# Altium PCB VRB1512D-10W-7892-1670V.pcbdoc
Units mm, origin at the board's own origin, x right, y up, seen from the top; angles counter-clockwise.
Board outline 80 x 45 mm, 2 copper layers (Top Layer, Bottom Layer), stack 0.78 mm thick; 36 components, 14 nets, 88 pads, 145 vias.
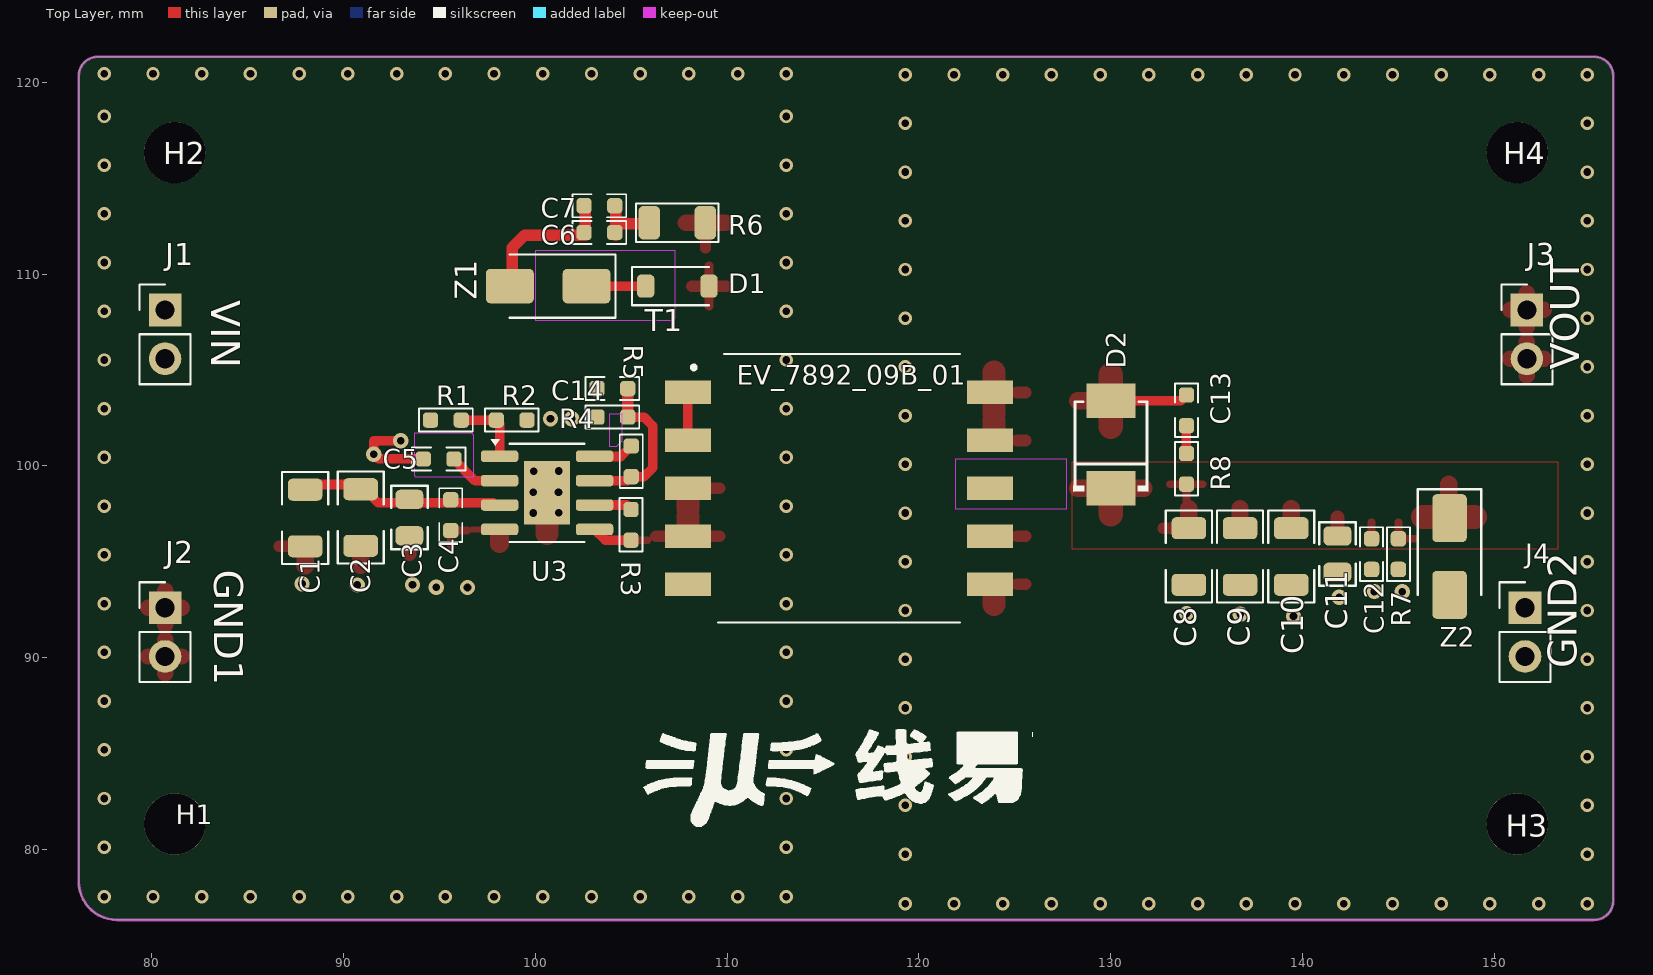
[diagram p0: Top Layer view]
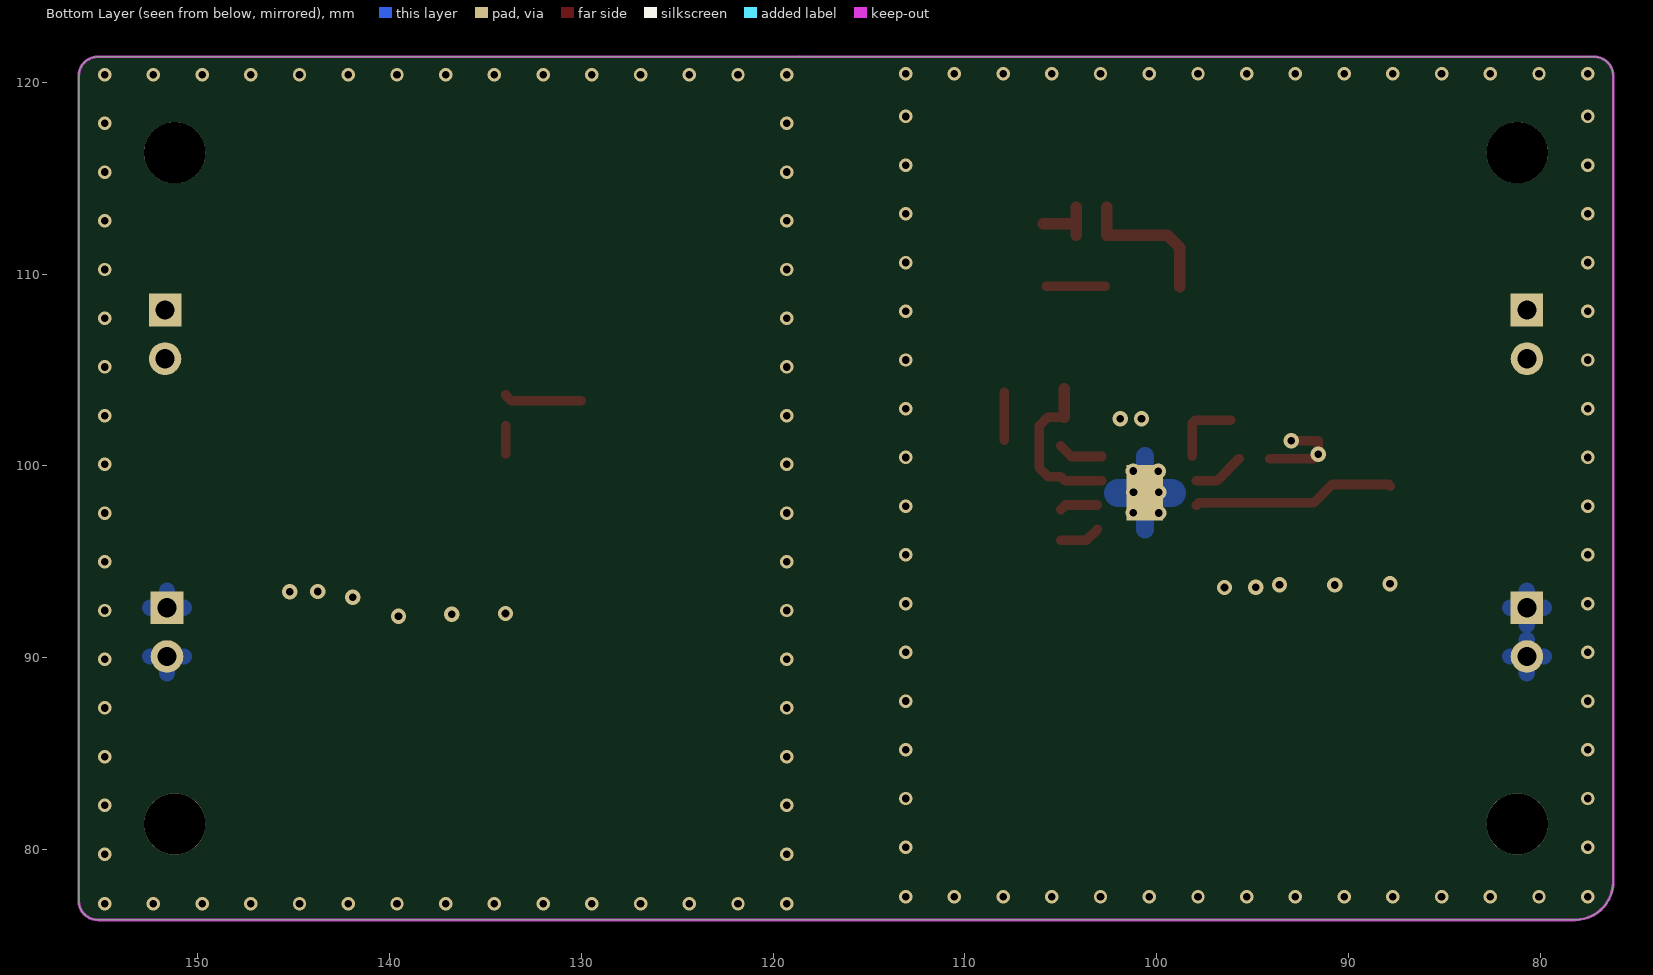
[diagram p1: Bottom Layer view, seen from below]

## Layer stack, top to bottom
Top Solder Mask Layer: solder mask 0.01, Dk 3.3
Top Layer: signal copper 0.035
Dielectric1: surface 0.71, FR4, Dk 4.5
Bottom Layer: signal copper 0.035
Bottom Solder Mask Layer: solder mask 0.01, Dk 3.3

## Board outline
76.2,120.327 cw(c77.2,120.327) 77.2,121.327 155.2,121.327 cw(c155.2,120.327) 156.2,120.327 156.2,77.327 cw(c155.2,77.327) 155.2,76.327 78.2,76.327 cw(c78.2,78.327) 76.2,78.327

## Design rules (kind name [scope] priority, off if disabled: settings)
BoardOutlineClearance safeClearance [All] p0: genericclearance=0.254 ignorepadtopadclearanceinfootprint=FALSE except(0: Arc-SplitContinuation Track-SplitContinuation SMDPad-SplitContinuation THPad-SplitContinuation Via-SplitContinuation Fill-SplitContinuation Poly-SplitContinuation Region-SplitContinuation Text-SplitContinuation)
BoardOutlineClearance Plane_innerPlane [All] p0: genericclearance=0.254 ignorepadtopadclearanceinfootprint=FALSE except(0: Arc-SplitContinuation Track-SplitContinuation SMDPad-SplitContinuation THPad-SplitContinuation Via-SplitContinuation Fill-SplitContinuation Poly-SplitContinuation Region-SplitContinuation Text-SplitContinuation)
BoardOutlineClearance Copper_CopperRegion [All] p0: genericclearance=0.254 ignorepadtopadclearanceinfootprint=FALSE except(0: Arc-SplitContinuation Track-SplitContinuation SMDPad-SplitContinuation THPad-SplitContinuation Via-SplitContinuation Fill-SplitContinuation Poly-SplitContinuation Region-SplitContinuation Text-SplitContinuation)
BoardOutlineClearance Copper_CopperRegion1 [All] p0: genericclearance=0.254 ignorepadtopadclearanceinfootprint=FALSE except(0: Arc-SplitContinuation Track-SplitContinuation SMDPad-SplitContinuation THPad-SplitContinuation Via-SplitContinuation Fill-SplitContinuation Poly-SplitContinuation Region-SplitContinuation Text-SplitContinuation)
BoardOutlineClearance Copper_CopperRegion2 [All] p0: genericclearance=0.254 ignorepadtopadclearanceinfootprint=FALSE except(0: Arc-SplitContinuation Track-SplitContinuation SMDPad-SplitContinuation THPad-SplitContinuation Via-SplitContinuation Fill-SplitContinuation Poly-SplitContinuation Region-SplitContinuation Text-SplitContinuation)
BoardOutlineClearance Copper_CopperRegion3 [All] p0: genericclearance=0.254 ignorepadtopadclearanceinfootprint=FALSE except(0: Arc-SplitContinuation Track-SplitContinuation SMDPad-SplitContinuation THPad-SplitContinuation Via-SplitContinuation Fill-SplitContinuation Poly-SplitContinuation Region-SplitContinuation Text-SplitContinuation)
BoardOutlineClearance Copper_CopperRegion4 [All] p0: genericclearance=0.254 ignorepadtopadclearanceinfootprint=FALSE except(0: Arc-SplitContinuation Track-SplitContinuation SMDPad-SplitContinuation THPad-SplitContinuation Via-SplitContinuation Fill-SplitContinuation Poly-SplitContinuation Region-SplitContinuation Text-SplitContinuation)
BoardOutlineClearance Copper_CopperRegion5 [All] p0: genericclearance=0.254 ignorepadtopadclearanceinfootprint=FALSE except(0: Arc-SplitContinuation Track-SplitContinuation SMDPad-SplitContinuation THPad-SplitContinuation Via-SplitContinuation Fill-SplitContinuation Poly-SplitContinuation Region-SplitContinuation Text-SplitContinuation)
BoardOutlineClearance Copper_CopperRegion6 [All] p0: genericclearance=0.254 ignorepadtopadclearanceinfootprint=FALSE except(0: Arc-SplitContinuation Track-SplitContinuation SMDPad-SplitContinuation THPad-SplitContinuation Via-SplitContinuation Fill-SplitContinuation Poly-SplitContinuation Region-SplitContinuation Text-SplitContinuation)
BoardOutlineClearance Copper_CopperRegion7 [All] p0: genericclearance=0.254 ignorepadtopadclearanceinfootprint=FALSE except(0: Arc-SplitContinuation Track-SplitContinuation SMDPad-SplitContinuation THPad-SplitContinuation Via-SplitContinuation Fill-SplitContinuation Poly-SplitContinuation Region-SplitContinuation Text-SplitContinuation)
BoardOutlineClearance Copper_CopperRegion8 [All] p0: genericclearance=0.254 ignorepadtopadclearanceinfootprint=FALSE except(0: Arc-SplitContinuation Track-SplitContinuation SMDPad-SplitContinuation THPad-SplitContinuation Via-SplitContinuation Fill-SplitContinuation Poly-SplitContinuation Region-SplitContinuation Text-SplitContinuation)
BoardOutlineClearance Copper_CopperRegion9 [All] p0: genericclearance=0.254 ignorepadtopadclearanceinfootprint=FALSE except(0: Arc-SplitContinuation Track-SplitContinuation SMDPad-SplitContinuation THPad-SplitContinuation Via-SplitContinuation Fill-SplitContinuation Poly-SplitContinuation Region-SplitContinuation Text-SplitContinuation)
BoardOutlineClearance Copper_CopperRegion10 [All] p0: genericclearance=0.254 ignorepadtopadclearanceinfootprint=FALSE except(0: Arc-SplitContinuation Track-SplitContinuation SMDPad-SplitContinuation THPad-SplitContinuation Via-SplitContinuation Fill-SplitContinuation Poly-SplitContinuation Region-SplitContinuation Text-SplitContinuation)
BoardOutlineClearance Copper_CopperRegion11 [All] p0: genericclearance=0.254 ignorepadtopadclearanceinfootprint=FALSE except(0: Arc-SplitContinuation Track-SplitContinuation SMDPad-SplitContinuation THPad-SplitContinuation Via-SplitContinuation Fill-SplitContinuation Poly-SplitContinuation Region-SplitContinuation Text-SplitContinuation)
BoardOutlineClearance otherClearance [All] p0: genericclearance=0.254 ignorepadtopadclearanceinfootprint=FALSE except(0: Arc-SplitContinuation Track-SplitContinuation SMDPad-SplitContinuation THPad-SplitContinuation Via-SplitContinuation Fill-SplitContinuation Poly-SplitContinuation Region-SplitContinuation Text-SplitContinuation)
Clearance safeClearance [All] p1: gap=0.178 ignorepadtopadclearanceinfootprint=FALSE
Clearance Plane_innerPlane [All] p1: gap=0.178 ignorepadtopadclearanceinfootprint=FALSE
Clearance Copper_CopperRegion [All] p1: gap=0.178 ignorepadtopadclearanceinfootprint=FALSE
Clearance Copper_CopperRegion1 [All] p1: gap=0.178 ignorepadtopadclearanceinfootprint=FALSE
Clearance Copper_CopperRegion2 [All] p1: gap=0.178 ignorepadtopadclearanceinfootprint=FALSE
Clearance Copper_CopperRegion3 [All] p1: gap=0.178 ignorepadtopadclearanceinfootprint=FALSE
Clearance Copper_CopperRegion4 [All] p1: gap=0.178 ignorepadtopadclearanceinfootprint=FALSE
Clearance Copper_CopperRegion5 [All] p1: gap=0.178 ignorepadtopadclearanceinfootprint=FALSE
Clearance Copper_CopperRegion6 [All] p1: gap=0.178 ignorepadtopadclearanceinfootprint=FALSE
Clearance Copper_CopperRegion7 [All] p1: gap=0.178 ignorepadtopadclearanceinfootprint=FALSE
Clearance Copper_CopperRegion8 [All] p1: gap=0.178 ignorepadtopadclearanceinfootprint=FALSE
Clearance Copper_CopperRegion9 [All] p1: gap=0.178 ignorepadtopadclearanceinfootprint=FALSE
Clearance Copper_CopperRegion10 [All] p1: gap=0.178 ignorepadtopadclearanceinfootprint=FALSE
Clearance Copper_CopperRegion11 [All] p1: gap=0.178 ignorepadtopadclearanceinfootprint=FALSE
Clearance otherClearance [All] p1: gap=0.178 ignorepadtopadclearanceinfootprint=FALSE
DiffPairsRouting differentialPair [All] p1: maxuncoupledlength=10 minlimit=6 maxlimit=Infinity mostfreqgap=6 toplayer_minwidth=5 toplayer_prefwidth=10 toplayer_maxwidth=100 bottomlayer_minwidth=5 bottomlayer_prefwidth=10 bottomlayer_maxwidth=100
PasteMaskExpansion Common [All] p1: expansion=0
PlaneConnect innerPlane [All] p1: planeconnectstyle=Relief reliefexpansion=0.508 reliefentries=4 reliefconductorwidth=0.254 reliefairgap=0.254
PolygonConnect CopperRegion [All] p1: connectstyle=Direct reliefentries=4 reliefconductorwidth=10 polygonreliefangle="90 Angle" airgapwidth=10
PolygonConnect CopperRegion1 [All] p1: connectstyle=Relief reliefentries=4 reliefconductorwidth=0 polygonreliefangle="90 Angle" airgapwidth=1
PolygonConnect CopperRegion2 [All] p1: connectstyle=Relief reliefentries=4 reliefconductorwidth=0 polygonreliefangle="90 Angle" airgapwidth=1
PolygonConnect CopperRegion3 [All] p1: connectstyle=Direct reliefentries=4 reliefconductorwidth=10 polygonreliefangle="90 Angle" airgapwidth=10
PolygonConnect CopperRegion4 [All] p1: connectstyle=Relief reliefentries=4 reliefconductorwidth=0 polygonreliefangle="90 Angle" airgapwidth=1
PolygonConnect CopperRegion5 [All] p1: connectstyle=Relief reliefentries=4 reliefconductorwidth=0 polygonreliefangle="90 Angle" airgapwidth=1
PolygonConnect CopperRegion6 [All] p1: connectstyle=Relief reliefentries=4 reliefconductorwidth=0 polygonreliefangle="90 Angle" airgapwidth=1
PolygonConnect CopperRegion7 [All] p1: connectstyle=Relief reliefentries=4 reliefconductorwidth=0 polygonreliefangle="90 Angle" airgapwidth=1
PolygonConnect CopperRegion8 [All] p1: connectstyle=Relief reliefentries=4 reliefconductorwidth=0 polygonreliefangle="90 Angle" airgapwidth=1
PolygonConnect CopperRegion9 [All] p1: connectstyle=Relief reliefentries=4 reliefconductorwidth=0 polygonreliefangle="90 Angle" airgapwidth=1
PolygonConnect CopperRegion10 [All] p1: connectstyle=Relief reliefentries=4 reliefconductorwidth=0 polygonreliefangle="90 Angle" airgapwidth=1
PolygonConnect CopperRegion11 [All] p1: connectstyle=Relief reliefentries=4 reliefconductorwidth=0 polygonreliefangle="90 Angle" airgapwidth=1
RoutingVias viaSize [All] p1: viastyle="Through Hole" holewidth=12 minholewidth=11.8 maxholewidth=236.2 width=12 minwidth=11.8 maxwidth=236.2
SolderMaskExpansion Common [All] p1: useseparateexpansions=TRUE expansion=0 expansionbottom=0
Width trackWidth [All] p1: maxlimit=100 minlimit=5 preferedwidth=10

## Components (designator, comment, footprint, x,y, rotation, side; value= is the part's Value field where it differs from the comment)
C1 "" MYLibrary:C1206 88.001,97.28 r270 top
C2 "" C1206 90.896,97.305 r270 top
C3 "" MYLibrary:C0805 93.436,97.305 r270 top
C4 "" C0603 95.595,97.432 r90 top
C5 "" C0603 94.96,100.353 r0 top
C6 "" C0603 103.342,112.164 r180 top
C7 "" MYLibrary:C0603 103.342,113.561 r180 top
C8 "" C1206 134.076,95.273 r270 top
C9 "" C1206 136.743,95.273 r270 top
C10 "" C1206 139.41,95.273 r270 top
C11 "" C0805 141.823,95.4 r270 top
C12 "" C0603 143.601,95.4 r90 top
C13 "" MYLibrary:C0603 133.949,102.893 r90 top
C14 "" C0603 104.02,104.027 r0 top
D1 "" SOD-123_L2.8-W1.8-LS3.7-FD 107.406,109.37 r0 top
D2 "" SMBF_L4.3-W3.6-LS5.3-RD 130.012,101.115 r90 top
H1 "Mechanical_MountingHole" MountingHole:MountingHole_3.2mm_M3_DIN965 81.2,81.327 r0 top
H2 "" MountingHole:MountingHole_3.2mm_M3_DIN965 81.2,116.327 r0 top
H3 "" MountingHole:MountingHole_3.2mm_M3_DIN965 151.2,81.327 r0 top
H4 "" MountingHole:MountingHole_3.2mm_M3_DIN965 151.2,116.327 r0 top
J1 "" ?#1 80.7,108.127 r0 top
J2 "" ?#1 80.7,92.602 r0 top
J3 "" ?#1 151.7,108.127 r0 top
J4 "Connector_Generic_Conn_01x02" Connector_PinHeader_2.54mm:PinHeader_1x02_P2.54mm_Vertical 151.6,92.602 r0 top
R1 "" R0603 95.341,102.385 r0 top
R2 "" MYLibrary:R0603 98.77,102.385 r0 top
R3 "" R0603 104.993,96.924 r270 top
R4 "" R0603 104.02,102.542 r180 top
R5 "" MYLibrary:R0603 105.005,100.237 r270 top
R6 "" R1206 107.406,112.672 r180 top
R7 "" R0603 144.998,95.4 r90 top
R8 "" MYLibrary:R0603 133.949,99.845 r90 top
T1 "" XFMR-SMD_CMB1670V 105.755,106.83 r0 top
U3 "" ?#2 96.916,101.293 r0 top
Z1 "" SMA_L4.4-W2.6-LS5.1-RD 100.675,109.37 r180 top
Z2 "" Diode_SMD:D_SMA 147.665,95.273 r270 top

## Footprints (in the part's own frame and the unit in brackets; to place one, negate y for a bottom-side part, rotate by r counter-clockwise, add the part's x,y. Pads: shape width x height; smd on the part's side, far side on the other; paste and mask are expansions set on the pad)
C0603 [mm]
  rrect50% 0.8x0.8 smd: 1(-0.8,0) 2(0.8,0)
  silkscreen extent -1.4,-0.6 1.4,0.6
C0805 [mm]
  rrect50% 1x1.45 smd: 1(-0.95,0) 2(0.95,0)
  silkscreen extent -1.65,-0.95 1.65,0.96
C1206 [mm]
  rrect43% 1.15x1.8 smd: 1(-1.475,0) 2(1.475,0)
  silkscreen extent -2.4,-1.2 2.4,1.2
Connector_PinHeader_2.54mm:PinHeader_1x02_P2.54mm_Vertical [mm]
  rect 1.7x1.7 hole 1: 1(0,0)
  round 1.7 hole 1: 2(0,-2.54)
  silkscreen extent -1.33,-3.87 1.33,1.33
Diode_SMD:D_SMA [mm]
  rrect27% 2.5x1.8 smd: 1(-2,0) 2(2,0)
  silkscreen extent -3.51,-1.65 2,1.65
MountingHole:MountingHole_3.2mm_M3_DIN965 [mm]
  round 3.2 hole 3.2 unplated: ""(0,0)
MYLibrary:C0603 [mm]
  rrect50% 0.8x0.8 smd: 1(-0.8,0) 2(0.8,0)
  silkscreen extent -1.4,-0.6 1.4,0.6
MYLibrary:C0805 [mm]
  rrect50% 1x1.45 smd: 1(-0.95,0) 2(0.95,0)
  silkscreen extent -1.65,-0.95 1.65,0.96
MYLibrary:C1206 [mm]
  rrect43% 1.15x1.8 smd: 1(-1.475,0) 2(1.475,0)
  silkscreen extent -2.4,-1.2 2.4,1.2
MYLibrary:R0603 [mm]
  rrect50% 0.8x0.8 smd: 1(-0.8,0) 2(0.8,0)
  silkscreen extent -1.4,-0.6 1.4,0.6
R0603 [mm]
  rrect50% 0.8x0.8 smd: 1(-0.8,0) 2(0.8,0)
  silkscreen extent -1.4,-0.6 1.4,0.6
R1206 [mm]
  rrect44% 1.125x1.75 smd: 1(-1.462,0) 2(1.462,0)
  silkscreen extent -2.15,-1 2.15,1
SMA_L4.4-W2.6-LS5.1-RD [mm]
  rrect27% 2.5x1.8 smd: 1(-2,0) 2(2,0)
  silkscreen extent -3.51,-1.65 2,1.65
SMBF_L4.3-W3.6-LS5.3-RD [mm]
  rect 1.8x2.54 smd: 1(-2.285,0) 2(2.285,0)
  silkscreen extent -2.45,-1.95 2.23,1.95
SOD-123_L2.8-W1.8-LS3.7-FD [mm]
  rrect50% 0.9x1.2 smd: 1(-1.65,0) 2(1.65,0)
  silkscreen extent -2.36,-1 1.65,1
XFMR-SMD_CMB1670V [mm]
  rect 2.4x1.22 smd: 1(2.2,-3) 2(2.2,-5.5) 3(2.2,-8) 4(2.2,-10.5) 5(2.2,-13) 6(17.96,-13) 7(17.96,-10.5) 8(17.96,-8) 9(17.96,-5.5) 10(17.96,-3)
  silkscreen extent 2.46,-15 16.38,-1
?#1 [mm]
  rect 1.7x1.7 hole 1: 1(0,0)
  round 1.7 hole 1: 2(0,-2.54)
  silkscreen extent -1.33,-3.87 1.33,1.33
?#2 [mm]
  rrect50% 1.95x0.6 smd: 1(1.225,-0.795) 2(1.225,-2.065) 3(1.225,-3.335) 4(1.225,-4.605) 5(6.175,-4.605) 6(6.175,-3.335) 7(6.175,-2.065) 8(6.175,-0.795)
  rect 2.41x3.3 smd: 9(3.7,-2.7)
  rect 1.9x2.9 smd far side: 9(3.7,-2.7)
  rrect49% 1.01x1.38 smd: ""(3.1,-3.525) ""(3.1,-1.875) ""(4.3,-3.525) ""(4.3,-1.875)
  silkscreen extent 0.76,-5.26 5.65,0.1

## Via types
v1: diameter 0.7, hole 0.4, Top Layer to Bottom Layer, 124 vias
v2: diameter 0.8, hole 0.4, Top Layer to Bottom Layer, 21 vias

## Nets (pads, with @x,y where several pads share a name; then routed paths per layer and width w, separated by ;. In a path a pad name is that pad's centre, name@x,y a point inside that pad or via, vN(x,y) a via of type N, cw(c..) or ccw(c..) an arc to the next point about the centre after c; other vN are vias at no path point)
$1N3972: C6.1 C7.1 R6.2 | length 3.2
  Top Layer w0.25: C6.1@104.192,112.017 C6.1@104.2,112.024
  Top Layer w0.6: C6.1@104.2,112.024 104.2,112.617 ; C7.1@104.2,113.477 104.2,112.617 ; R6.2@105.907,112.617 104.2,112.617
$1N3986: D1.1 Z1.1 | length 3.1
  Top Layer w0.5: Z1.1 D1.1
$1N4011: R1.2 R2.1 U3.1 | length 3.8
  Top Layer w0.5: R1.2 R2.1 98.141,102.214 U3.1
$1N4023: R3.1 U3.6 | length 2
  Top Layer w0.5: U3.6 104.76,97.958 R3.1
$1N4278: C5.2 U3.2 | length 2.7
  Top Layer w0.5: C5.2@95.705,100.377 96.865,99.217 U3.2@97.925,99.217
$1N4425: C13.1 R8.2 | length 1.4
  Top Layer w0.5: R8.2 C13.1
/SEC: C13.2 D2.2 T1.9 T1.10 | length 4.1
  Top Layer w0.5: D2.2 133.656,103.4 C13.2
GND1: C1.2 C2.2 C3.2 C4.1 C5.1 C14.1 J2.1 J2.2 R2.2 R4.2 U3. U3.4 U3.9 | length 4.7
  Top Layer w0.5: v2(92.985,101.307) 91.585,101.307 v2(91.585,100.607) 91.815,100.377 C5.1@94.105,100.377
  other v1: 77.53,77.527 80.07,77.527 82.61,77.527 85.15,77.527 87.69,77.527 90.23,77.527 92.77,77.527 95.31,77.527 97.85,77.527 100.39,77.527 102.93,77.527 105.47,77.527 108.01,77.527 110.55,77.527 113.09,77.527 77.53,80.117 113.09,80.117 77.53,82.657 113.09,82.657 77.53,85.197 113.09,85.197 77.53,87.737 113.09,87.737 77.53,90.277 113.09,90.277 77.53,92.817 113.09,92.817 77.53,95.357 113.09,95.357 77.53,97.897 113.09,97.897 77.53,100.437 113.09,100.437 77.53,102.977 113.09,102.977 77.53,105.517 113.09,105.517 77.53,108.057 113.09,108.057 77.53,110.597 113.09,110.597 77.53,113.137 113.09,113.137 77.53,115.677 113.09,115.677 77.53,118.217 113.09,118.217 77.53,120.44 80.07,120.44 82.61,120.44 85.15,120.44 87.69,120.44 90.23,120.44 92.77,120.44 95.31,120.44 97.85,120.44 100.39,120.44 102.93,120.44 105.47,120.44 108.01,120.44 110.55,120.44 113.09,120.44
  other v2: 96.465,93.657 94.835,93.677 90.715,93.787 93.6,93.797 87.835,93.857 99.894,97.54 101.216,97.55 99.894,98.629 101.213,98.629 99.913,99.718 101.216,99.728 100.795,102.447 101.895,102.447
GND2: C8.2 C9.2 C10.2 C11.2 C12.1 J4.1 J4.2 R7.1 T1.6 T1.7 Z2.2
  other v1: 119.29,77.167 121.83,77.167 124.37,77.167 126.91,77.167 129.45,77.167 131.99,77.167 134.53,77.167 137.07,77.167 139.61,77.167 142.15,77.167 144.69,77.167 147.23,77.167 149.77,77.167 152.31,77.167 154.85,77.167 119.29,79.757 154.85,79.757 119.29,82.297 154.85,82.297 119.29,84.837 154.85,84.837 119.29,87.377 154.85,87.377 119.29,89.917 154.85,89.917 119.29,92.457 154.85,92.457 119.29,94.997 154.85,94.997 119.29,97.537 154.85,97.537 119.29,100.077 154.85,100.077 119.29,102.617 154.85,102.617 119.29,105.157 154.85,105.157 119.29,107.697 154.85,107.697 119.29,110.237 154.85,110.237 119.29,112.777 154.85,112.777 119.29,115.317 154.85,115.317 119.29,117.857 154.85,117.857 119.29,120.397 121.83,120.397 124.37,120.397 126.91,120.397 129.45,120.397 131.99,120.397 134.53,120.397 137.07,120.397 139.61,120.397 142.15,120.397 144.69,120.397 147.23,120.397 149.77,120.397 152.31,120.397 154.85,120.397
  other v2: 139.53,92.164 136.75,92.254 133.95,92.304 141.92,93.154 143.74,93.448 145.2,93.438
RREF: C14.2 R4.1 R5.2 U3.7 | length 8.7
  Top Layer w0.5: U3.7@102.875,99.217 104.785,99.217 R5.2 105.665,99.437 106.125,99.897 106.125,102.087 105.67,102.542 R4.1
  Top Layer w0.6: R4.1 C14.2
SW: D1.2 R3.2 R6.1 T1.3 T1.4 U3.5 | length 2.1
  Top Layer w0.5: U3.5 103.655,96.124 R3.2
TC: R5.1 U3.8 | length 2.4
  Top Layer w0.5: U3.8@102.875,100.487 104.455,100.487 R5.1
VIN: C1.1 C2.1 C3.1 C4.2 C6.2 C7.2 J1.1 J1.2 R1.1 T1.1 T1.2 U3.3 Z1.2 | length 20.6
  Top Layer w0.5: C1.1@87.825,98.942 87.912,99.029 90.855,99.029 91.81,98.074 97.798,98.074 U3.3@97.925,97.947 ; T1.2 T1.1
  Top Layer w0.6: Z1.2@98.787,109.347 98.787,111.364 99.44,112.017 102.592,112.017 102.6,112.024 C7.2@102.6,113.477
VOUT: C8.1 C9.1 C10.1 C11.1 C12.2 D2.1 J3.1 J3.2 R7.2 R8.1 Z2.1
pads on no net: H1. H2. H3. H4. T1.5 T1.8

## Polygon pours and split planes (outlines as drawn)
VOUT on Top Layer (solid, remove dead copper, pour order 0): 153.5,109.927 153.5,95.657 127.799,95.657 127.799,99.6 148.19,99.6 148.19,109.367 148.75,109.927
GND2 on Bottom Layer (solid, remove dead copper, pour order 20): 118.219,121.2 155.819,121.2 155.819,76.2 118.219,76.2
GND2 on Bottom Layer (solid, remove dead copper, pour order 22): 118.542,121.327 118.6,121.327 118.6,121.385
SW on Top Layer (solid, remove dead copper, pour order 2): 106.87,99.437 109.64,99.437 109.895,99.697 109.895,105.587 107.395,108.087 107.395,112.937 107.955,113.497 110.368,113.497 111.505,112.36 111.505,96.357 110.595,95.447 102.14,95.447 101.9,95.687 101.9,96.887 101.96,96.947 106.165,96.947 106.87,97.917
/SEC on Top Layer (solid, remove dead copper, pour order 4): 122.31,106.197 131.88,106.197 131.88,100.537 122.31,100.537
GND1 on Top Layer (solid, remove dead copper, pour order 6): 99.195,104.527 103.895,104.527 103.895,101.347 101.895,101.347 101.695,101.147 101.695,100.322 101.505,100.132 101.505,99.407 101.445,99.347 99.695,99.347 99.295,99.747 99.295,100.489
GND1 on Top Layer (solid, remove dead copper, pour order 8): 90.985,101.807 93.705,101.807 93.705,99.877 90.985,99.877
VIN on Top Layer (solid, remove dead copper, pour order 10): 78.9,111.137 109.358,111.137 109.358,97.657 78.9,97.657
GND2 on Top Layer (solid, remove dead copper, pour order 12): 122.16,97.257 126.39,97.257 126.39,90.667 122.16,90.667
GND1 on Top Layer (solid, remove dead copper, pour order 14): 76.2,121.327 113.858,121.327 113.858,76.327 76.2,76.327
GND1 on Bottom Layer (solid, remove dead copper, pour order 24): 76.2,121.327 113.858,121.327 113.858,76.327 76.2,76.327
GND2 on Top Layer (solid, remove dead copper, pour order 16): 118.796,121.417 156.454,121.417 156.454,76.327 118.796,76.327
VOUT on Top Layer (solid, remove dead copper, pour order 18): 127.997,100.207 153.32,100.207 153.32,95.657 127.997,95.657

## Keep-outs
Top Layer:
  region: 103.89,102.717 104.52,102.717 104.52,101.287 104.23,100.997 103.89,100.997
  region: 103.88,102.717 103.89,102.717 103.89,102.727
  region: 93.755,99.427 96.785,99.427 96.785,101.607 96.685,101.707 93.685,101.707 93.685,99.497
  region: 100.037,111.227 107.267,111.227 107.267,107.679 107.155,107.567 101.72,107.567 100.037,107.567
  region: 127.67,100.367 127.67,97.747 121.93,97.747 121.93,100.367
Board Outline Layer:
  the board outline again, w0.15

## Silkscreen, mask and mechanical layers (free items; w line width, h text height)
Top Silkscreen Layer:
  drawing of 10 lines, arcs and shapes, not listed
  text "VIN" at 83.1,108.637 h1.5 r270
  text "VOUT" at 154.42,105.017 h1.5 r90
  text "EV_7892_09B_01" at 110.5,104.227 h1
  text "GND1" at 83.26,94.587 h1.5 r270
  text "GND2" at 154.31,89.437 h1.5 r90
